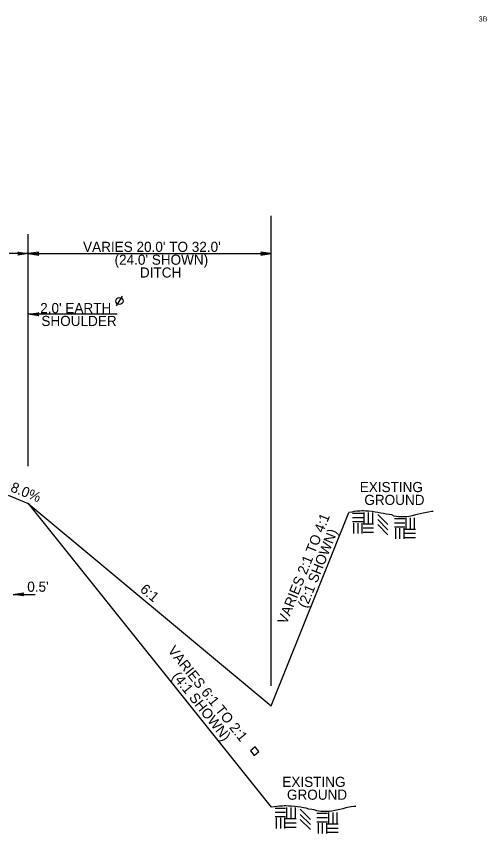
# Model space of a CAD drawing. Extents: x 2003207 to 2014043, y 843846 to 860154.
# Drawn here: x 2013735.7 to 2013782.1, y 844708.7 to 844789.4 of the extents above; entities that cross this region are included whole.
import ezdxf

# ---------------------------------------------------------------- set-up
doc = ezdxf.new("R2010")
doc.units = 0
for name, color, linetype in [('RD_EX_Road_txCode', 7, 'Continuous'), ('RD_QTY_PermVeg', 7, 'Continuous'), ('RD_SHT_TX', 7, 'Continuous'), ('RD_TX_TypSect', 7, 'Continuous'), ('RD_XS_ExGround', 7, 'Continuous')]:
    doc.layers.add(name, color=color, linetype=linetype)

msp = doc.modelspace()

# ---------------------------------------------------------------- linework, layer by layer
at = {"layer": 'RD_EX_Road_txCode'}
msp.add_lwpolyline([(2013758.793, 844716.865), (2013759.171, 844716.399), (2013759.637, 844716.778), (2013759.259, 844717.244)], close=True, dxfattribs=at)
at = {"layer": 'RD_QTY_PermVeg'}
for p, q in [((2013734.86, 844742.092), (2013736.86, 844741.292)), ((2013736.86, 844741.292), (2013760.86, 844721.292)), ((2013736.86, 844741.292), (2013760.86, 844711.292)), ((2013760.86, 844721.292), (2013768.503, 844740.399))]:
    msp.add_line(p, q, dxfattribs=at)
at = {"layer": 'RD_TX_TypSect'}
for p, q in [((2013760.86, 844723.292), (2013760.86, 844769.668)), ((2013736.86, 844744.953), (2013736.86, 844767.863)), ((2013736.86, 844765.956), (2013722.86, 844765.956)), ((2013736.86, 844765.956), (2013760.86, 844765.956)), ((2013745.582, 844760.794), (2013746.148, 844761.737)), ((2013745.647, 844759.956), (2013736.86, 844759.956)), ((2013735.36, 844732.3), (2013737.527, 844732.3))]:
    msp.add_line(p, q, dxfattribs=at)
for points in [[(2013736.86, 844765.956), (2013735.821, 844765.806), (2013735.981, 844765.956), (2013735.821, 844766.106)], [(2013736.86, 844765.956), (2013737.898, 844765.806), (2013737.739, 844765.956), (2013737.898, 844766.106)], [(2013760.86, 844765.956), (2013759.821, 844766.106), (2013759.981, 844765.956), (2013759.821, 844765.806)], [(2013736.86, 844759.956), (2013737.898, 844760.106), (2013737.739, 844759.956), (2013737.898, 844759.806)], [(2013735.36, 844732.3), (2013736.398, 844732.45), (2013736.239, 844732.3), (2013736.398, 844732.15)]]:
    msp.add_lwpolyline(points, close=True, dxfattribs=at)
msp.add_circle((2013745.865, 844761.266), 0.35, dxfattribs=at)
at = {"layer": 'RD_XS_ExGround'}
for p, q in [((2013769.916, 844740.287), (2013768.874, 844740.287)), ((2013769.916, 844739.87), (2013768.874, 844739.87)), ((2013770.012, 844740.384), (2013770.012, 844739.342)), ((2013770.429, 844740.384), (2013770.429, 844739.342)), ((2013770.846, 844740.384), (2013770.846, 844739.342)), ((2013772.368, 844739.193), (2013771.368, 844740.193)), ((2013774.149, 844739.865), (2013774.149, 844738.824)), ((2013774.565, 844739.865), (2013774.565, 844738.824)), ((2013774.982, 844739.865), (2013774.982, 844738.824)), ((2013769.916, 844739.454), (2013768.874, 844739.454)), ((2013768.979, 844739.349), (2013768.979, 844738.308)), ((2013769.395, 844739.349), (2013769.395, 844738.308)), ((2013769.812, 844739.349), (2013769.812, 844738.308)), ((2013770.958, 844739.245), (2013769.916, 844739.245)), ((2013772.368, 844738.693), (2013771.368, 844739.693)), ((2013772.368, 844738.193), (2013771.368, 844739.193)), ((2013774.052, 844739.768), (2013773.011, 844739.768)), ((2013774.052, 844739.352), (2013773.011, 844739.352)), ((2013770.958, 844738.829), (2013769.916, 844738.829)), ((2013770.958, 844738.412), (2013769.916, 844738.412)), ((2013774.052, 844738.935), (2013773.011, 844738.935)), ((2013773.115, 844738.831), (2013773.115, 844737.789)), ((2013773.531, 844738.831), (2013773.531, 844737.789)), ((2013773.948, 844738.831), (2013773.948, 844737.789)), ((2013775.094, 844738.727), (2013774.052, 844738.727)), ((2013775.094, 844738.31), (2013774.052, 844738.31)), ((2013775.094, 844737.893), (2013774.052, 844737.893)), ((2013762.273, 844711.18), (2013761.231, 844711.18)), ((2013762.37, 844711.277), (2013762.37, 844710.235)), ((2013762.786, 844711.277), (2013762.786, 844710.235)), ((2013763.203, 844711.277), (2013763.203, 844710.235)), ((2013764.725, 844710.086), (2013763.725, 844711.086)), ((2013762.273, 844710.763), (2013761.231, 844710.763)), ((2013762.273, 844710.346), (2013761.231, 844710.346)), ((2013761.336, 844710.242), (2013761.336, 844709.2)), ((2013761.752, 844710.242), (2013761.752, 844709.2)), ((2013762.169, 844710.242), (2013762.169, 844709.2)), ((2013763.315, 844710.138), (2013762.273, 844710.138)), ((2013764.725, 844709.586), (2013763.725, 844710.586)), ((2013764.725, 844709.086), (2013763.725, 844710.086)), ((2013766.409, 844710.661), (2013765.368, 844710.661)), ((2013766.409, 844710.244), (2013765.368, 844710.244)), ((2013766.506, 844710.758), (2013766.506, 844709.716)), ((2013766.922, 844710.758), (2013766.922, 844709.716)), ((2013767.339, 844710.758), (2013767.339, 844709.716)), ((2013763.315, 844709.721), (2013762.273, 844709.721)), ((2013763.315, 844709.305), (2013762.273, 844709.305)), ((2013766.409, 844709.828), (2013765.368, 844709.828)), ((2013765.472, 844709.724), (2013765.472, 844708.682)), ((2013765.889, 844709.724), (2013765.889, 844708.682)), ((2013766.305, 844709.724), (2013766.305, 844708.682)), ((2013767.451, 844709.619), (2013766.409, 844709.619)), ((2013767.451, 844709.203), (2013766.409, 844709.203)), ((2013767.451, 844708.786), (2013766.409, 844708.786))]:
    msp.add_line(p, q, dxfattribs=at)
for points in [[(2013776.84, 844740.473), (2013776.665, 844740.473), (2013776.373, 844740.436), (2013776.19, 844740.399), (2013775.86, 844740.326), (2013775.567, 844740.253), (2013775.274, 844740.18), (2013775.091, 844740.143), (2013774.762, 844740.07), (2013774.469, 844739.997), (2013774.25, 844739.96), (2013774.067, 844739.96), (2013773.847, 844739.96), (2013773.627, 844739.96), (2013773.408, 844739.96), (2013773.188, 844739.997), (2013773.005, 844740.033), (2013772.749, 844740.143), (2013772.493, 844740.18), (2013772.2, 844740.216), (2013771.944, 844740.29), (2013771.687, 844740.326), (2013771.394, 844740.399), (2013771.102, 844740.436), (2013770.809, 844740.473), (2013770.479, 844740.509), (2013770.187, 844740.509), (2013769.967, 844740.546), (2013769.784, 844740.546), (2013769.601, 844740.509), (2013769.308, 844740.509), (2013769.052, 844740.473), (2013768.796, 844740.436), (2013768.503, 844740.399)], [(2013769.197, 844711.365), (2013769.022, 844711.365), (2013768.73, 844711.329), (2013768.547, 844711.292), (2013768.217, 844711.219), (2013767.924, 844711.146), (2013767.632, 844711.072), (2013767.449, 844711.036), (2013767.119, 844710.962), (2013766.826, 844710.889), (2013766.607, 844710.853), (2013766.424, 844710.853), (2013766.204, 844710.853), (2013765.984, 844710.853), (2013765.765, 844710.853), (2013765.545, 844710.889), (2013765.362, 844710.926), (2013765.106, 844711.036), (2013764.85, 844711.072), (2013764.557, 844711.109), (2013764.301, 844711.182), (2013764.044, 844711.219), (2013763.752, 844711.292), (2013763.459, 844711.329), (2013763.166, 844711.365), (2013762.836, 844711.402), (2013762.544, 844711.402), (2013762.324, 844711.439), (2013762.141, 844711.439), (2013761.958, 844711.402), (2013761.665, 844711.402), (2013761.409, 844711.365), (2013761.153, 844711.329), (2013760.86, 844711.292)]]:
    msp.add_lwpolyline(points, dxfattribs=at)

# ---------------------------------------------------------------- texts
at = {"layer": 'RD_SHT_TX'}
msp.add_text('3B', height=0.5, dxfattribs=at).set_placement((2013781.344, 844788.867))
at = {"layer": 'RD_TX_TypSect'}
for s, p in [("VARIES 20.0' TO 32.0'", (2013742.27, 844766.119)), ("(24.0' SHOWN)", (2013745.38, 844764.851)), ('DITCH', (2013747.884, 844763.584)), ("2.0' EARTH", (2013738.036, 844760.069)), ('SHOULDER', (2013738.154, 844758.802)), ('EXISTING', (2013769.591, 844742.404)), ('GROUND', (2013770.047, 844741.136)), ("0.5'", (2013736.758, 844732.564)), ('EXISTING', (2013761.948, 844713.297)), ('GROUND', (2013762.404, 844712.029))]:
    msp.add_text(s, height=1, dxfattribs=at).set_placement(p)
for s, rotation, p in [('8.0%', 338.19859, (2013735.026, 844742.503)), ('VARIES 2:1 TO 4:1', 68.19859, (2013762.363, 844729.282)), ('(2:1 SHOWN)', 68.19859, (2013764.365, 844730.873)), ('6:1', 319.76842, (2013747.823, 844732.668)), ('VARIES 6:1 TO 2:1', 308.65981, (2013750.577, 844726.741)), ('(4:1 SHOWN)', 308.65981, (2013751.004, 844724.178))]:
    msp.add_text(s, height=1, rotation=rotation, dxfattribs=at).set_placement(p)

doc.saveas('drawing.dxf')
